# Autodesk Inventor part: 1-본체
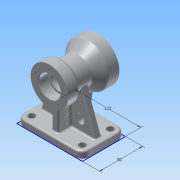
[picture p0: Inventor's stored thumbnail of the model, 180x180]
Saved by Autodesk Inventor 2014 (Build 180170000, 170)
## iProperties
Created: 2015-08
Part Number: 1-본체
Material: 알루미늄 6061
Document SubType Name: Modeling
Designer: study
Density: 2.71 g/cm^3
Appearance: 알루미늄 - 평지
Mass: 1062.79 g
Surface Area: 749.652 cm^2
Volume: 392.172 cm^3
Author: study
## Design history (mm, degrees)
sketch "스케치1"
  geometry: L1 (61, -40)-(-61, -40); L2 (-61, -40)-(-61, 40); L3 (-61, 40)-(61, 40); L4 (61, 40)-(61, -40); L5 (61, -40)-(-61, 40); L6 (-61, -40)-(61, 40); 1 further point
  constraints: 12 end point, 2 midpoint, 2 parallel, 1 horizontal, 1 perpendicular
  dimensions: "d0" = 122 distance of L2.end L3.end; "d1" = 80 distance of L3.end L1.start
extrude "돌출1" new body sketch "스케치1" distance "d2" = 12; taper "d3" = 0 deg
sketch "스케치4"
  geometry: 1 further point
sketch "스케치5"
  geometry: L1 (-40, 90)-(50, 90); L2 (-40, 0)-(-40, 12) reference; L3 (-40, 90)-(-40, 125); L4 (-40, 125)-(-20, 125); L5 (-20, 125)-(-14.804, 116); L6 (-14.804, 116)-(13.315, 116); L7 (13.315, 116)-(30, 130); L8 (30, 130)-(50, 130); L9 (50, 130)-(50, 90); L10 (40, 0)-(-40, 0) reference; 1 further point
  constraints: 16 end point, 2 parallel, 2 perpendicular, 1 horizontal, 1 vertical, 1 vertical alignment
  dimensions: "d15" = 90 distance of L1.start L1.end; "d16" = 70 diameter of L4 L1; "d17" = 20 distance from line of L4.end L3; "d18" = 60 deg angle of L6 L5; "d19" = 52 diameter of L6 L1; "d20" = 80 diameter of L8 L1; "d21" = 20 distance from line of L9 L7.end; "d22" = 40 deg angle of L6 L7; "d23" = 90 distance from line of L10 L1.end
revolve "회전2" sketch "스케치5" stored, may be unused: angle "d24" = 90 deg
sketch "스케치7"
  geometry: L1 (-61, 12)-(61, 12) reference; L2 (-51, 12)-(-20, 97.172); L3 (-20, 97.172)-(20, 97.172); L4 (20, 97.172)-(51, 12); L5 (-51, 12)-(51, 12); L6 (61, 0)-(-61, 0) reference; L7 (61, 0)-(61, 12) reference; 3 further points
  constraints: 8 end point, 2 midpoint, 2 parallel, 2 point on line, 1 vertical alignment
  dimensions: "d45" = 70 deg angle of L5 L2; "d47" = 70 deg angle of L4 L1; "d48" = 10 distance from line of L4.end L7; "d49" = 40 distance of L2.end L3.end
extrude "돌출2" join sketch "스케치7" stored distance "d50" = 12; taper "d51" = 0 deg
sketch "스케치8"
  geometry: L1 (-40, 12)-(40, 12) reference; L2 (-30, 12)-(-30, 85.727); L3 (-30, 85.727)-(43, 85.727); L4 (43, 85.727)-(30, 12); L5 (-30, 12)-(30, 12); L6 (-40, 0)-(-40, 12) reference; L7 (40, 0)-(40, 12) reference; 1 further point
  constraints: 8 end point, 2 perpendicular, 2 point on line, 1 collinear
  dimensions: "d52" = 10 distance from line of L2.start L6; "d53" = 10 distance from line of L4.end L7; "d54" = 80 deg angle of L1 L4; "d55" = 73 distance of L2.end L3.end
extrude "돌출3" join sketch "스케치8" stored distance "d56" = 12; taper "d57" = 0 deg
hole "구멍1" diameter "d27" = 32; stored, may be unused: countersink angle "d31" = 90 deg, drill point angle "d33" = 0 deg; dims "d28" = 6, "d29" = 40, "d30" = 17, "d32" = 23, "d34" = 10, "d35" = 10
hole "구멍2" diameter "d38" = 38; stored, may be unused: countersink angle "d42" = 90 deg, drill point angle "d44" = 0 deg; dims "d36" = 10, "d37" = 10, "d39" = 6, "d40" = 52, "d41" = 20, "d43" = 23
sketch "스케치9"
  geometry: L1 (-55.518, -30)-(-12, -30) reference; L2 (0, 40)-(0, -40) reference; L3 (-12, -40)-(-12, 40) reference; 2 further points
  constraints: 1 other
  dimensions: "d59" = 16 distance from line of point (-36, -14) L1; "d60" = 24 distance from line of L3 point (-36, -14)
feature "엠보싱1" sketch "스케치9" dims "d0" = 122, "d1" = 80, "d61" = 0.5, "d62" = 0
fillet "모깎기1" dims "d63" = 14, "d64" = 0.3, "d65" = 3
fillet "모깎기2" dims "d66" = 3
fillet "모깎기3" dims "d67" = 3, "d95" = 5
fillet "모깎기4" dims "d68" = 3
sketch "스케치10"
  geometry: L1 (9, -62.432)-(9, -15) reference; L2 (30, -36)-(30, -30); L3 (18, -30)-(18, -36); L4 (-18, -36)-(-18, -30); L5 (-30, -30)-(-30, -36); L6 (58, -12)-(47, -12) reference; L7 (24, -30)-(-24, -30); A1 r 6 centre (24, -30) between (30, -30) and (18, -30); A2 r 6 centre (24, -36) between (18, -36) and (30, -36); A3 r 6 centre (-24, -30) between (-18, -30) and (-30, -30); A4 r 6 centre (-24, -36) between (-30, -36) and (-18, -36); 2 further points
  constraints: 10 end point, 8 point on circle, 8 tangent, 5 parallel, 4 centre point, 2 horizontal alignment, 1 midpoint, 1 vertical alignment
  dimensions: "d69" = 18 distance from line of L7.start L6; "d70" = 18 dimension on A1 A2; "d71" = 12 distance between parallel lines of L3 L2; "d72" = 48 distance of L7.end L7.start; "d73" = 12 distance between parallel lines of L5 L4
extrude "돌출4" cut sketch "스케치10" stored distance "d74" = 12; taper "d75" = 0 deg
sketch "스케치11" dims "d76" = 66
  geometry: C1 r 26 at (0, 0) reference; C2 r 40 at (0, 0) reference; 3 further points
  constraints: 2 vertical alignment, 1 coincident, 2 other
hole "구멍3" sketch "스케치11" at (0, -33) diameter "d77" = 3.242; stored, may be unused: countersink angle "d81" = 90 deg, drill point angle "d83" = 118 deg; dims "d78" = 10, "d79" = 52, "d80" = 20, "d82" = 13
sketch "스케치12" dims "d87" = 54
  geometry: C1 r 20 at (0, 0) reference; C2 r 35 at (0, 0) reference; 3 further points
  constraints: 2 vertical alignment, 1 coincident, 2 other
hole "구멍4" sketch "스케치12" at (0, 27) diameter "d88" = 3.242; stored, may be unused: countersink angle "d92" = 90 deg, drill point angle "d94" = 118 deg; dims "d89" = 10, "d90" = 52, "d91" = 20, "d93" = 13
chamfer "모따기1" distance "d99" = 1; stored, may be unused: second distance "d100" = 2, angle "d101" = 45 deg
sketch "스케치13"
  geometry: L1 (47, -26)-(-47, -26); L2 (-47, -26)-(-47, 26); L3 (-47, 26)-(47, 26); L4 (47, 26)-(47, -26); L5 (47, -26)-(-47, 26); L6 (-47, -26)-(47, 26); 7 further points
  constraints: 12 end point, 5 coincident, 3 midpoint, 2 parallel, 1 horizontal, 1 perpendicular
  dimensions: "d102" = 94 distance of L2.end L3.end; "d103" = 52 distance of L3.end L1.start
hole "구멍5" sketch "스케치13" at (-47, 26), (-47, -26), (47, -26), (47, 26) diameter "d104" = 12; stored, may be unused: countersink angle "d108" = 90 deg, drill point angle "d110" = 118 deg; dims "d105" = 10, "d106" = 52, "d107" = 20, "d109" = 13
node "솔리드1"
pattern_circular "원형 패턴1" dims angle "d85" = 360 deg
pattern_circular "원형 패턴2" dims angle "d97" = 360 deg
